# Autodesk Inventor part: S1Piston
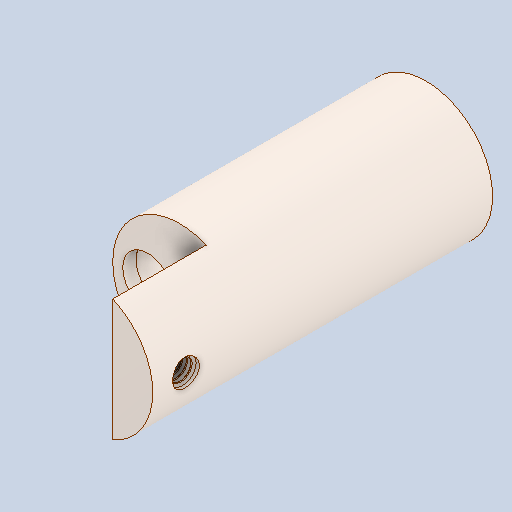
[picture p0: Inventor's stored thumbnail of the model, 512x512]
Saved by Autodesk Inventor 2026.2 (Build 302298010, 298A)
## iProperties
Created: 1601-01
Part Number: S1Piston
Material: 201 Annealed Stainless Steel (SS)
Document SubType Name: Modeling
Designer: mel
Density: 7.86 g/cm^3
Appearance: satin finish stainless steel
Author: mel
Sending System: SOLIDWORKS 2023
Part Number: Piston
Last Saved Date: 2025-04-02
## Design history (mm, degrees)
feature "Chanfrein1"
node "Plan1"
node "Solide1"
